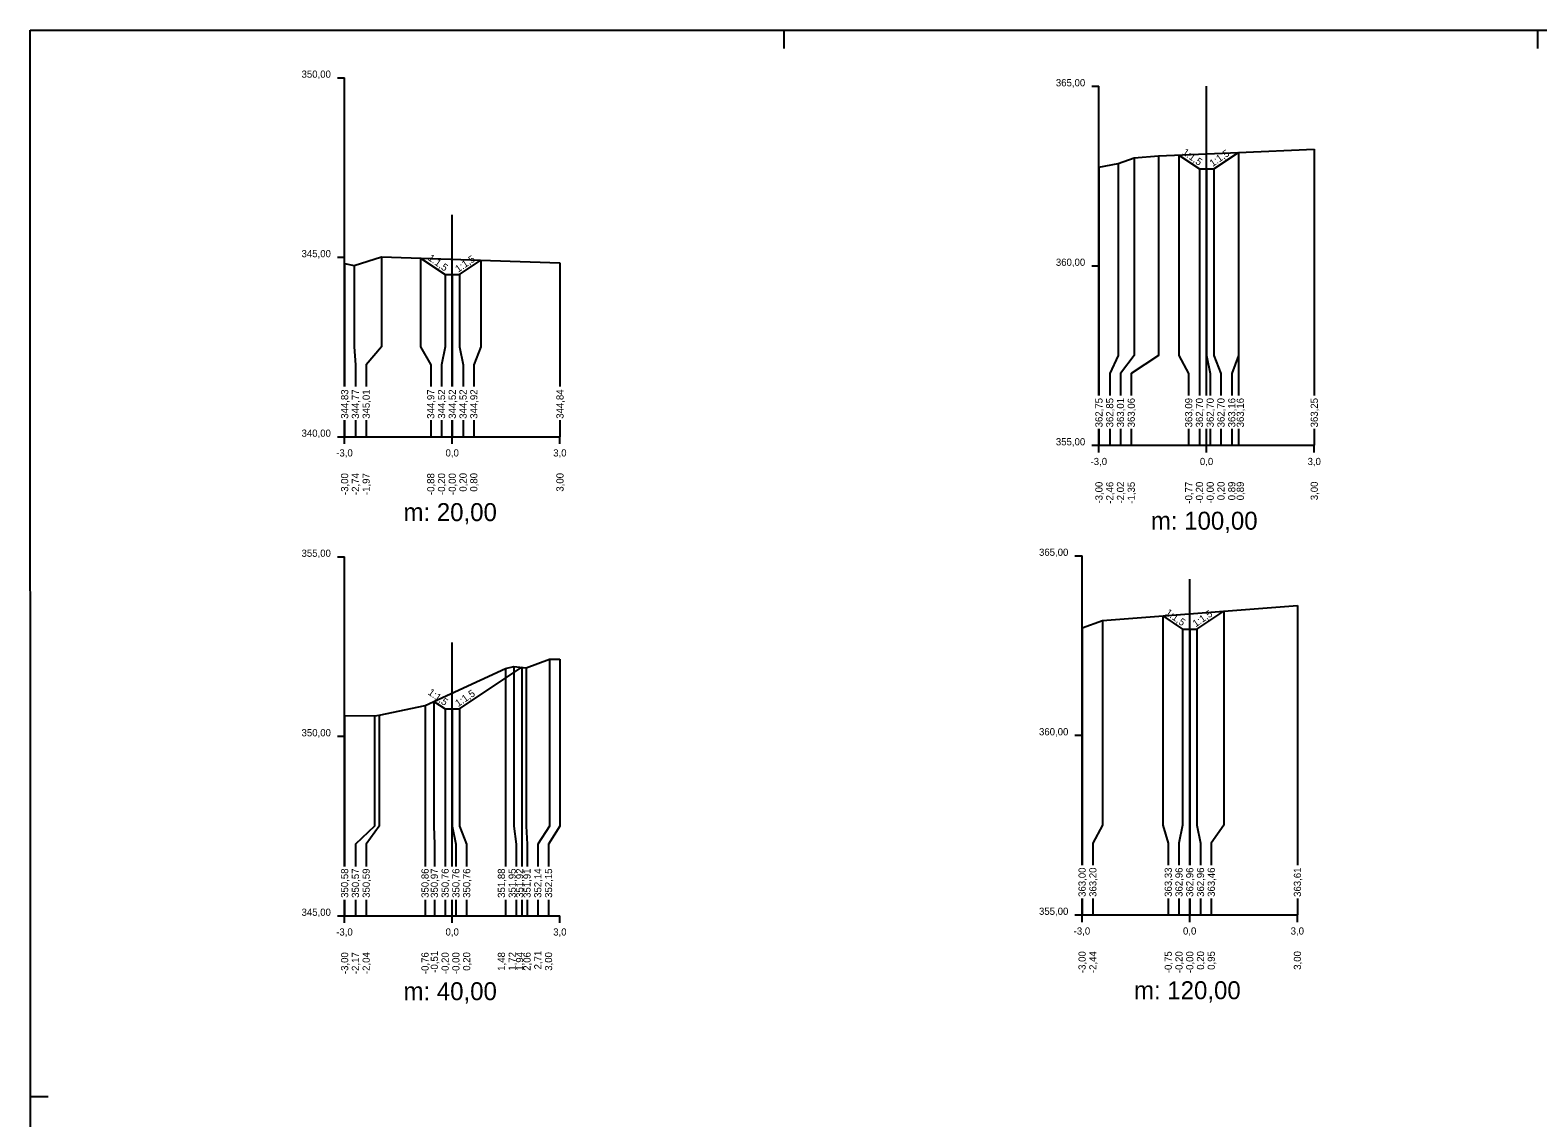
# Model space of a CAD drawing. Extents: x -497367.2 to -497283.2, y -1136708.7 to -1136649.3.
# Drawn here: x -497367.25 to -497325.24, y -1136679.63 to -1136649.33 of the extents above; entities that cross this region are included whole.
import ezdxf

# ---------------------------------------------------------------- set-up
doc = ezdxf.new("R2010")
doc.units = 0
for name, color, linetype in [('11', 7, 'Continuous'), ('16', 7, 'Continuous'), ('21', 7, 'Continuous'), ('28', 7, 'Continuous'), ('59', 7, 'Continuous'), ('8', 7, 'Continuous'), ('Vrstva 63', 7, 'Continuous')]:
    doc.layers.add(name, color=color, linetype=linetype)

msp = doc.modelspace()

# ---------------------------------------------------------------- linework, layer by layer
for points in [[(-497337.468, -1136653.147), (-497336.933, -1136653.049), (-497336.483, -1136652.889), (-497335.813, -1136652.838), (-497333.576, -1136652.737), (-497331.468, -1136652.644)], [(-497335.241, -1136652.812), (-497334.668, -1136653.195), (-497334.468, -1136653.195), (-497334.268, -1136653.195), (-497333.582, -1136652.737)], [(-497334.664, -1136653.195), (-497334.668, -1136653.195), (-497334.668, -1136653.194)], [(-497334.27, -1136653.195), (-497334.268, -1136653.195), (-497334.268, -1136653.194)], [(-497358.486, -1136655.83), (-497358.223, -1136655.89), (-497357.455, -1136655.646), (-497352.486, -1136655.816)], [(-497356.369, -1136655.685), (-497356.369, -1136655.683), (-497356.368, -1136655.681)], [(-497356.369, -1136655.683), (-497355.686, -1136656.138), (-497355.486, -1136656.138), (-497355.286, -1136656.138), (-497354.69, -1136655.741)], [(-497354.69, -1136655.743), (-497354.69, -1136655.741), (-497354.69, -1136655.739)], [(-497355.686, -1136656.14), (-497355.686, -1136656.138), (-497355.686, -1136656.136)], [(-497355.286, -1136656.14), (-497355.286, -1136656.138), (-497355.286, -1136656.136)], [(-497337.938, -1136665.978), (-497337.373, -1136665.777), (-497331.938, -1136665.362)], [(-497335.692, -1136665.649), (-497335.138, -1136666.018), (-497334.938, -1136666.018), (-497334.738, -1136666.018), (-497333.989, -1136665.518)], [(-497335.138, -1136666.018), (-497335.138, -1136666.018), (-497335.138, -1136666.018)], [(-497334.738, -1136666.018), (-497334.738, -1136666.018), (-497334.738, -1136666.018)], [(-497358.486, -1136668.427), (-497357.657, -1136668.432), (-497357.527, -1136668.413), (-497356.246, -1136668.142), (-497354.004, -1136667.117), (-497353.767, -1136667.055), (-497353.431, -1136667.095), (-497352.778, -1136666.857), (-497352.486, -1136666.85)], [(-497356, -1136668.03), (-497355.686, -1136668.239), (-497355.486, -1136668.239), (-497355.286, -1136668.239), (-497353.549, -1136667.081)], [(-497355.686, -1136668.241), (-497355.686, -1136668.239), (-497355.686, -1136668.236)], [(-497355.286, -1136668.241), (-497355.286, -1136668.239), (-497355.286, -1136668.236)]]:
    msp.add_lwpolyline(points)
at = {"layer": '11'}
for points in [[(-497336.483, -1136652.889), (-497336.483, -1136658.397), (-497336.868, -1136658.897), (-497336.868, -1136659.507)], [(-497335.813, -1136652.838), (-497335.813, -1136658.397), (-497336.568, -1136658.897), (-497336.568, -1136659.507)], [(-497335.241, -1136652.812), (-497335.241, -1136658.397), (-497334.968, -1136658.897), (-497334.968, -1136659.507)], [(-497333.582, -1136652.737), (-497333.582, -1136658.397), (-497333.768, -1136658.897), (-497333.768, -1136659.507)], [(-497333.576, -1136652.737), (-497333.576, -1136658.397), (-497333.576, -1136658.897), (-497333.576, -1136659.507)], [(-497331.468, -1136652.644), (-497331.468, -1136658.397), (-497331.468, -1136658.897), (-497331.468, -1136659.507)], [(-497337.468, -1136653.147), (-497337.468, -1136658.397), (-497337.468, -1136658.897), (-497337.468, -1136659.507)], [(-497336.933, -1136653.049), (-497336.933, -1136658.397), (-497337.168, -1136658.897), (-497337.168, -1136659.507)], [(-497334.668, -1136653.195), (-497334.668, -1136658.397), (-497334.668, -1136658.897), (-497334.668, -1136659.507)], [(-497334.468, -1136653.195), (-497334.468, -1136658.397), (-497334.368, -1136658.897), (-497334.368, -1136659.507)], [(-497334.268, -1136653.195), (-497334.268, -1136658.397), (-497334.068, -1136658.897), (-497334.068, -1136659.507)], [(-497358.486, -1136655.83), (-497358.486, -1136658.158), (-497358.486, -1136658.658), (-497358.486, -1136659.258)], [(-497357.455, -1136655.646), (-497357.455, -1136658.158), (-497357.886, -1136658.658), (-497357.886, -1136659.258)], [(-497356.369, -1136655.683), (-497356.369, -1136658.158), (-497356.086, -1136658.658), (-497356.086, -1136659.258)], [(-497354.69, -1136655.741), (-497354.69, -1136658.158), (-497354.886, -1136658.658), (-497354.886, -1136659.258)], [(-497352.486, -1136655.816), (-497352.486, -1136658.158), (-497352.486, -1136658.658), (-497352.486, -1136659.258)], [(-497358.223, -1136655.89), (-497358.223, -1136658.158), (-497358.186, -1136658.658), (-497358.186, -1136659.258)], [(-497355.686, -1136656.138), (-497355.686, -1136658.158), (-497355.786, -1136658.658), (-497355.786, -1136659.258)], [(-497355.486, -1136656.138), (-497355.486, -1136658.158), (-497355.486, -1136658.658), (-497355.486, -1136659.258)], [(-497355.286, -1136656.138), (-497355.286, -1136658.158), (-497355.186, -1136658.658), (-497355.186, -1136659.258)], [(-497358.486, -1136660.192), (-497358.486, -1136660.658)], [(-497358.186, -1136660.192), (-497358.186, -1136660.658)], [(-497357.886, -1136660.192), (-497357.886, -1136660.658)], [(-497356.086, -1136660.192), (-497356.086, -1136660.658)], [(-497355.786, -1136660.192), (-497355.786, -1136660.658)], [(-497355.486, -1136660.192), (-497355.486, -1136660.658)], [(-497355.186, -1136660.192), (-497355.186, -1136660.658)], [(-497354.886, -1136660.192), (-497354.886, -1136660.658)], [(-497352.486, -1136660.192), (-497352.486, -1136660.658)], [(-497337.468, -1136660.441), (-497337.468, -1136660.897)], [(-497337.168, -1136660.441), (-497337.168, -1136660.897)], [(-497336.868, -1136660.441), (-497336.868, -1136660.897)], [(-497336.568, -1136660.441), (-497336.568, -1136660.897)], [(-497334.968, -1136660.441), (-497334.968, -1136660.897)], [(-497334.668, -1136660.441), (-497334.668, -1136660.897)], [(-497334.368, -1136660.441), (-497334.368, -1136660.897)], [(-497334.068, -1136660.441), (-497334.068, -1136660.897)], [(-497333.768, -1136660.441), (-497333.768, -1136660.897)], [(-497333.576, -1136660.441), (-497333.576, -1136660.897)], [(-497331.468, -1136660.441), (-497331.468, -1136660.897)], [(-497333.989, -1136665.518), (-497333.989, -1136671.475), (-497334.338, -1136671.975), (-497334.338, -1136672.588)], [(-497331.938, -1136665.362), (-497331.938, -1136671.475), (-497331.938, -1136671.975), (-497331.938, -1136672.588)], [(-497337.373, -1136665.777), (-497337.373, -1136671.475), (-497337.638, -1136671.975), (-497337.638, -1136672.588)], [(-497335.692, -1136665.649), (-497335.692, -1136671.475), (-497335.538, -1136671.975), (-497335.538, -1136672.588)], [(-497337.938, -1136665.978), (-497337.938, -1136671.475), (-497337.938, -1136671.975), (-497337.938, -1136672.588)], [(-497335.138, -1136666.018), (-497335.138, -1136671.475), (-497335.238, -1136671.975), (-497335.238, -1136672.588)], [(-497334.938, -1136666.018), (-497334.938, -1136671.475), (-497334.938, -1136671.975), (-497334.938, -1136672.588)], [(-497334.738, -1136666.018), (-497334.738, -1136671.475), (-497334.638, -1136671.975), (-497334.638, -1136672.588)], [(-497354.004, -1136667.117), (-497354.004, -1136671.502), (-497354.004, -1136672.002), (-497354.004, -1136672.624)], [(-497353.767, -1136667.055), (-497353.767, -1136671.502), (-497353.704, -1136672.002), (-497353.704, -1136672.624)], [(-497353.549, -1136667.081), (-497353.549, -1136671.502), (-497353.549, -1136672.002), (-497353.549, -1136672.624)], [(-497353.431, -1136667.095), (-497353.431, -1136671.502), (-497353.404, -1136672.002), (-497353.404, -1136672.624)], [(-497352.778, -1136666.857), (-497352.778, -1136671.502), (-497353.104, -1136672.002), (-497353.104, -1136672.624)], [(-497352.486, -1136666.85), (-497352.486, -1136671.502), (-497352.804, -1136672.002), (-497352.804, -1136672.624)], [(-497356, -1136668.03), (-497356, -1136671.502), (-497355.986, -1136672.002), (-497355.986, -1136672.624)], [(-497358.486, -1136668.427), (-497358.486, -1136671.502), (-497358.486, -1136672.002), (-497358.486, -1136672.624)], [(-497357.657, -1136668.432), (-497357.657, -1136671.502), (-497358.186, -1136672.002), (-497358.186, -1136672.624)], [(-497357.527, -1136668.413), (-497357.527, -1136671.502), (-497357.886, -1136672.002), (-497357.886, -1136672.624)], [(-497356.246, -1136668.142), (-497356.246, -1136671.502), (-497356.246, -1136672.002), (-497356.246, -1136672.624)], [(-497355.686, -1136668.239), (-497355.686, -1136671.502), (-497355.686, -1136672.002), (-497355.686, -1136672.624)], [(-497355.486, -1136668.239), (-497355.486, -1136671.502), (-497355.386, -1136672.002), (-497355.386, -1136672.624)], [(-497355.286, -1136668.239), (-497355.286, -1136671.502), (-497355.086, -1136672.002), (-497355.086, -1136672.624)], [(-497358.486, -1136673.558), (-497358.486, -1136674.002)], [(-497358.186, -1136673.558), (-497358.186, -1136674.002)], [(-497357.886, -1136673.558), (-497357.886, -1136674.002)], [(-497356.246, -1136673.558), (-497356.246, -1136674.002)], [(-497355.986, -1136673.558), (-497355.986, -1136674.002)], [(-497355.686, -1136673.558), (-497355.686, -1136674.002)], [(-497355.386, -1136673.558), (-497355.386, -1136674.002)], [(-497355.086, -1136673.558), (-497355.086, -1136674.002)], [(-497354.004, -1136673.558), (-497354.004, -1136674.002)], [(-497353.704, -1136673.558), (-497353.704, -1136674.002)], [(-497353.549, -1136673.558), (-497353.549, -1136674.002)], [(-497353.404, -1136673.558), (-497353.404, -1136674.002)], [(-497353.104, -1136673.558), (-497353.104, -1136674.002)], [(-497352.804, -1136673.558), (-497352.804, -1136674.002)], [(-497337.938, -1136673.522), (-497337.938, -1136673.975)], [(-497337.638, -1136673.522), (-497337.638, -1136673.975)], [(-497335.538, -1136673.522), (-497335.538, -1136673.975)], [(-497335.238, -1136673.522), (-497335.238, -1136673.975)], [(-497334.938, -1136673.522), (-497334.938, -1136673.975)], [(-497334.638, -1136673.522), (-497334.638, -1136673.975)], [(-497334.338, -1136673.522), (-497334.338, -1136673.975)], [(-497331.938, -1136673.522), (-497331.938, -1136673.975)]]:
    msp.add_lwpolyline(points, dxfattribs=at)
at = {"layer": '16'}
for p, q in [((-497358.486, -1136660.658), (-497352.486, -1136660.658)), ((-497337.468, -1136660.897), (-497331.468, -1136660.897)), ((-497358.486, -1136674.002), (-497352.486, -1136674.002)), ((-497337.938, -1136673.975), (-497331.938, -1136673.975))]:
    msp.add_line(p, q, dxfattribs=at)
for points in [[(-497334.468, -1136653.195), (-497334.468, -1136653.195), (-497334.468, -1136653.194)], [(-497355.486, -1136656.14), (-497355.486, -1136656.138), (-497355.486, -1136656.136)], [(-497334.938, -1136666.018), (-497334.938, -1136666.018), (-497334.938, -1136666.018)], [(-497355.486, -1136668.241), (-497355.486, -1136668.239), (-497355.486, -1136668.236)]]:
    msp.add_lwpolyline(points, dxfattribs=at)
at = {"layer": '21'}
for p, q in [((-497358.686, -1136650.658), (-497358.486, -1136650.658)), ((-497337.668, -1136650.897), (-497337.468, -1136650.897)), ((-497358.686, -1136655.658), (-497358.486, -1136655.658)), ((-497337.668, -1136655.897), (-497337.468, -1136655.897)), ((-497358.686, -1136660.658), (-497358.486, -1136660.658)), ((-497337.668, -1136660.897), (-497337.468, -1136660.897)), ((-497358.686, -1136664.002), (-497358.486, -1136664.002)), ((-497338.138, -1136663.975), (-497337.938, -1136663.975)), ((-497358.686, -1136669.002), (-497358.486, -1136669.002)), ((-497338.138, -1136668.975), (-497337.938, -1136668.975)), ((-497358.686, -1136674.002), (-497358.486, -1136674.002)), ((-497338.138, -1136673.975), (-497337.938, -1136673.975))]:
    msp.add_line(p, q, dxfattribs=at)
at = {"layer": '28'}
for p, q in [((-497334.468, -1136659.507), (-497334.468, -1136650.897)), ((-497355.486, -1136659.258), (-497355.486, -1136654.474)), ((-497355.486, -1136660.658), (-497355.486, -1136660.192)), ((-497334.468, -1136660.897), (-497334.468, -1136660.441)), ((-497334.938, -1136672.588), (-497334.938, -1136664.629)), ((-497355.486, -1136672.624), (-497355.486, -1136666.387)), ((-497355.486, -1136674.002), (-497355.486, -1136673.558)), ((-497334.938, -1136673.975), (-497334.938, -1136673.522))]:
    msp.add_line(p, q, dxfattribs=at)
at = {"layer": '59'}
for p, q in [((-497358.486, -1136660.858), (-497358.486, -1136660.658)), ((-497355.486, -1136660.858), (-497355.486, -1136660.658)), ((-497352.486, -1136660.858), (-497352.486, -1136660.658)), ((-497337.468, -1136661.097), (-497337.468, -1136660.897)), ((-497334.468, -1136661.097), (-497334.468, -1136660.897)), ((-497331.468, -1136661.097), (-497331.468, -1136660.897)), ((-497358.486, -1136674.202), (-497358.486, -1136674.002)), ((-497355.486, -1136674.202), (-497355.486, -1136674.002)), ((-497352.486, -1136674.202), (-497352.486, -1136674.002)), ((-497337.938, -1136674.175), (-497337.938, -1136673.975)), ((-497334.938, -1136674.175), (-497334.938, -1136673.975)), ((-497331.938, -1136674.175), (-497331.938, -1136673.975))]:
    msp.add_line(p, q, dxfattribs=at)
at = {"layer": '8'}
for p, q in [((-497358.486, -1136659.258), (-497358.486, -1136650.658)), ((-497337.468, -1136659.507), (-497337.468, -1136650.897)), ((-497358.486, -1136660.658), (-497358.486, -1136660.192)), ((-497337.468, -1136660.897), (-497337.468, -1136660.441)), ((-497358.486, -1136672.624), (-497358.486, -1136664.002)), ((-497337.938, -1136672.588), (-497337.938, -1136663.975)), ((-497358.486, -1136674.002), (-497358.486, -1136673.558)), ((-497337.938, -1136673.975), (-497337.938, -1136673.522))]:
    msp.add_line(p, q, dxfattribs=at)
at = {"layer": 'Vrstva 63'}
for p, q in [((-497367.248, -1136649.335), (-497283.248, -1136649.333)), ((-497367.238, -1136708.736), (-497367.248, -1136649.335)), ((-497346.239, -1136649.84), (-497346.239, -1136649.337)), ((-497325.239, -1136649.84), (-497325.239, -1136649.337)), ((-497367.243, -1136679.035), (-497366.743, -1136679.035)), ((-497367.243, -1136679.035), (-497366.743, -1136679.035))]:
    msp.add_line(p, q, dxfattribs=at)

# ---------------------------------------------------------------- texts
at = {"layer": '16'}
for s, p in [('344,83', (-497358.386, -1136660.158)), ('344,77', (-497358.086, -1136660.158)), ('345,01', (-497357.786, -1136660.158)), ('344,97', (-497355.986, -1136660.158)), ('344,52', (-497355.686, -1136660.158)), ('344,52', (-497355.386, -1136660.158)), ('344,52', (-497355.086, -1136660.158)), ('344,92', (-497354.786, -1136660.158)), ('344,84', (-497352.386, -1136660.158)), ('362,75', (-497337.368, -1136660.397)), ('362,85', (-497337.068, -1136660.397)), ('363,01', (-497336.768, -1136660.397)), ('363,06', (-497336.468, -1136660.397)), ('363,09', (-497334.868, -1136660.397)), ('362,70', (-497334.568, -1136660.397)), ('362,70', (-497334.268, -1136660.397)), ('362,70', (-497333.968, -1136660.397)), ('363,16', (-497333.668, -1136660.397)), ('363,16', (-497333.429, -1136660.397)), ('363,25', (-497331.368, -1136660.397)), ('350,58', (-497358.386, -1136673.502)), ('350,57', (-497358.086, -1136673.502)), ('350,59', (-497357.786, -1136673.502)), ('350,86', (-497356.146, -1136673.502)), ('350,97', (-497355.886, -1136673.502)), ('350,76', (-497355.586, -1136673.502)), ('350,76', (-497355.286, -1136673.502)), ('350,76', (-497354.986, -1136673.502)), ('351,88', (-497354.017, -1136673.502)), ('351,95', (-497353.717, -1136673.502)), ('351,92', (-497353.51, -1136673.502)), ('351,91', (-497353.304, -1136673.502)), ('352,14', (-497353.004, -1136673.502)), ('352,15', (-497352.704, -1136673.502)), ('363,00', (-497337.838, -1136673.475)), ('363,20', (-497337.538, -1136673.475)), ('363,33', (-497335.438, -1136673.475)), ('362,96', (-497335.138, -1136673.475)), ('362,96', (-497334.838, -1136673.475)), ('362,96', (-497334.538, -1136673.475)), ('363,46', (-497334.238, -1136673.475)), ('363,61', (-497331.838, -1136673.475))]:
    msp.add_text(s, height=0.2, rotation=90, dxfattribs=at).set_placement(p)
at = {"layer": '21'}
for s, p in [('350,00', (-497359.686, -1136650.658)), ('365,00', (-497338.668, -1136650.897)), ('345,00', (-497359.686, -1136655.658)), ('360,00', (-497338.668, -1136655.897)), ('340,00', (-497359.686, -1136660.658)), ('355,00', (-497338.668, -1136660.897)), ('-3,0', (-497358.72, -1136661.208)), ('0,0', (-497355.674, -1136661.208)), ('3,0', (-497352.674, -1136661.208)), ('-3,0', (-497337.702, -1136661.447)), ('0,0', (-497334.655, -1136661.447)), ('3,0', (-497331.655, -1136661.447)), ('355,00', (-497359.686, -1136664.002)), ('365,00', (-497339.138, -1136663.975)), ('350,00', (-497359.686, -1136669.002)), ('360,00', (-497339.138, -1136668.975)), ('345,00', (-497359.686, -1136674.002)), ('355,00', (-497339.138, -1136673.975)), ('-3,0', (-497338.172, -1136674.525)), ('0,0', (-497335.126, -1136674.525)), ('3,0', (-497332.126, -1136674.525)), ('-3,0', (-497358.72, -1136674.552)), ('0,0', (-497355.674, -1136674.552)), ('3,0', (-497352.674, -1136674.552))]:
    msp.add_text(s, height=0.2, dxfattribs=at).set_placement(p)
for rotation, p in [(324.91, (-497335.164, -1136652.776)), (34.4489, (-497334.301, -1136653.146)), (324.91, (-497356.183, -1136655.72)), (34.4489, (-497355.32, -1136656.09)), (324.91, (-497335.635, -1136665.6)), (34.4489, (-497334.772, -1136665.97)), (324.91, (-497356.183, -1136667.821)), (34.4489, (-497355.32, -1136668.19))]:
    msp.add_text('1:1,5', height=0.2, rotation=rotation, dxfattribs=at).set_placement(p)
at = {"layer": '28'}
for s, p in [('m: 20,00', (-497356.845, -1136663.008)), ('m: 100,00', (-497336.021, -1136663.247)), ('m: 40,00', (-497356.845, -1136676.352)), ('m: 120,00', (-497336.491, -1136676.325))]:
    msp.add_text(s, height=0.5, dxfattribs=at).set_placement(p)
at = {"layer": '59'}
for s, p in [('-3,00', (-497358.386, -1136662.281)), ('-2,74', (-497358.086, -1136662.281)), ('-1,97', (-497357.786, -1136662.282)), ('-0,88', (-497355.986, -1136662.282)), ('-0,20', (-497355.686, -1136662.281)), ('-0,00', (-497355.386, -1136662.281)), ('0,20', (-497355.086, -1136662.188)), ('0,80', (-497354.786, -1136662.188)), ('3,00', (-497352.386, -1136662.188)), ('-3,00', (-497337.368, -1136662.52)), ('-2,46', (-497337.068, -1136662.521)), ('-2,02', (-497336.768, -1136662.519)), ('-1,35', (-497336.468, -1136662.523)), ('-0,77', (-497334.868, -1136662.521)), ('-0,20', (-497334.568, -1136662.52)), ('-0,00', (-497334.268, -1136662.52)), ('0,20', (-497333.968, -1136662.427)), ('0,89', (-497333.668, -1136662.429)), ('0,89', (-497333.429, -1136662.429)), ('3,00', (-497331.368, -1136662.427)), ('-3,00', (-497358.386, -1136675.626)), ('-2,17', (-497358.086, -1136675.626)), ('-2,04', (-497357.786, -1136675.625)), ('-0,76', (-497356.146, -1136675.626)), ('-0,51', (-497355.886, -1136675.588)), ('-0,20', (-497355.586, -1136675.626)), ('-0,00', (-497355.286, -1136675.626)), ('0,20', (-497354.986, -1136675.533)), ('1,48', (-497354.017, -1136675.534)), ('1,72', (-497353.717, -1136675.531)), ('1,94', (-497353.51, -1136675.532)), ('2,06', (-497353.304, -1136675.533)), ('2,71', (-497353.004, -1136675.495)), ('3,00', (-497352.704, -1136675.533)), ('-3,00', (-497337.838, -1136675.598)), ('-2,44', (-497337.538, -1136675.598)), ('-0,75', (-497335.438, -1136675.6)), ('-0,20', (-497335.138, -1136675.598)), ('-0,00', (-497334.838, -1136675.598)), ('0,20', (-497334.538, -1136675.505)), ('0,95', (-497334.238, -1136675.507)), ('3,00', (-497331.838, -1136675.505))]:
    msp.add_text(s, height=0.2, rotation=90, dxfattribs=at).set_placement(p)

doc.saveas('drawing.dxf')
